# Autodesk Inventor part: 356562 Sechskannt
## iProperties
Company: Mayer & Müller AG Schaltgeräte
Created: 2006-04
Part Number: 356562 Sechskannt
Material: 1.0718.07
Document SubType Name: Modeling
Designer: I.Baliuc
Description: Haltebolzen
Density: 7.84 g/cm^3
HalbzeugNorm: DIN 176
Zweck: Vorkontakt HSLT
Abmessung: Skt. 22 - 72
Author: T.Messerschmitt
Keywords: 266417
Revision Number: 356562
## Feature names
1. Extrusion2_SW22-72
2. Drehung1 [Revolution]
3. Bohrung_M10 / 20 tief [Hole]
4. Spiegeln1 [Mirror]
